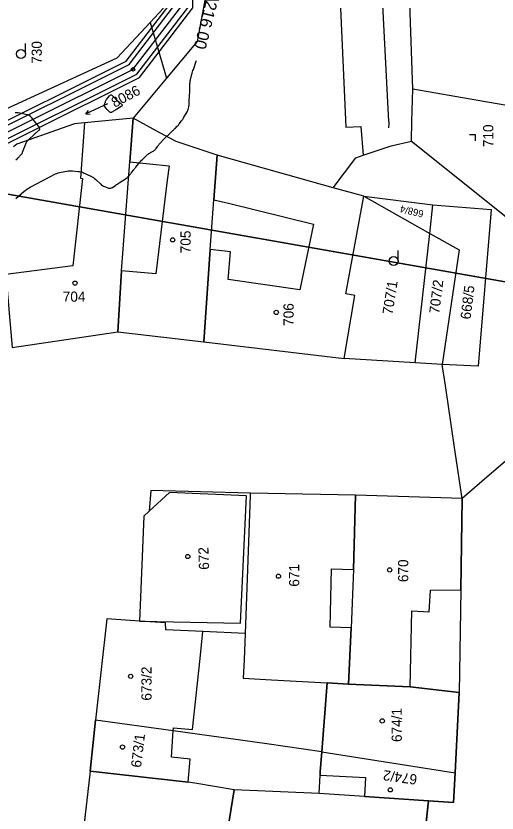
# Model space of a CAD drawing. Extents: x -534481 to -534262, y -1190577 to -1190138.
# Drawn here: x -534365.7 to -534325.5, y -1190410 to -1190343.4 of the extents above; entities that cross this region are included whole.
import ezdxf

# ---------------------------------------------------------------- set-up
doc = ezdxf.new("R2010")
doc.units = 0
for name, color, linetype in [('Bonity', 7, 'Continuous'), ('Definiční body', 7, 'Continuous'), ('Polygon budovy', 7, 'Continuous'), ('Polygon parcely', 7, 'Continuous'), ('Vrstva 17', 7, 'Continuous'), ('Vrstva 18', 7, 'Continuous'), ('Vrstva 19', 7, 'Continuous'), ('Vrstva 30', 7, 'Continuous'), ('Vrstva 32', 7, 'Continuous'), ('Vrstva 37', 7, 'Continuous'), ('Vrstva 46', 7, 'Continuous'), ('Vrstva 48', 7, 'Continuous')]:
    doc.layers.add(name, color=color, linetype=linetype)

msp = doc.modelspace()

# ---------------------------------------------------------------- linework, layer by layer
at = {"layer": 'Bonity'}
msp.add_lwpolyline([(-534409.868, -1190391.439), (-534405.947, -1190382.816), (-534400.873, -1190377.487), (-534393.696, -1190372.718), (-534384.927, -1190365.477), (-534382.631, -1190361.148), (-534355.894, -1190347.823), (-534351.738, -1190342.389), (-534351.577, -1190328.316), (-534347.204, -1190300.921), (-534345.553, -1190283.64), (-534344.682, -1190264.494)], dxfattribs=at)
at = {"layer": 'Definiční body'}
for p, q in [((-534353.09, -1190348.56), (-534355.88, -1190351.91)), ((-534336.63, -1190358.42), (-534339.19, -1190357.71)), ((-534336.63, -1190358.42), (-534330.85, -1190359.15)), ((-534336.63, -1190358.42), (-534331.12, -1190361.52)), ((-534331.12, -1190361.52), (-534330.85, -1190359.15)), ((-534332.34, -1190372.35), (-534331.12, -1190361.52)), ((-534365.97, -1190371.05), (-534357.17, -1190369.75)), ((-534357.17, -1190369.75), (-534349.98, -1190370.59)), ((-534349.98, -1190370.59), (-534338.27, -1190371.97)), ((-534332.34, -1190372.35), (-534338.27, -1190371.97)), ((-534330.07, -1190372.49), (-534332.34, -1190372.35)), ((-534337.31, -1190383.4), (-534346.1, -1190383.23)), ((-534328.4, -1190383.66), (-534337.31, -1190383.4)), ((-534358.08, -1190393.72), (-534359.01, -1190402.18)), ((-534355.36, -1190393.91), (-534358.08, -1190393.72)), ((-534340.13, -1190404.83), (-534339.69, -1190399.07)), ((-534339.69, -1190399.07), (-534337.9, -1190399.17)), ((-534328.66, -1190399.89), (-534329, -1190406.6)), ((-534359.48, -1190406.45), (-534359.01, -1190402.18)), ((-534340.26, -1190406.48), (-534340.13, -1190404.83)), ((-534340.13, -1190404.83), (-534329, -1190406.6)), ((-534359.48, -1190406.45), (-534361.32, -1190422.75)), ((-534340.34, -1190408.33), (-534347.45, -1190408.02)), ((-534331.23, -1190408.93), (-534332.91, -1190424.36))]:
    msp.add_line(p, q, dxfattribs=at)
for points in [[(-534349.69, -1190337.24), (-534349.69, -1190337.44), (-534349.9, -1190342.02), (-534350.53, -1190345.48), (-534353.09, -1190348.56)], [(-534332.53, -1190349.48), (-534332.78, -1190342.31), (-534332.83, -1190337.12)], [(-534354.46, -1190343.91), (-534353.36, -1190342.74), (-534353.4, -1190337.34)], [(-534374.45, -1190354.76), (-534357.22, -1190346.86), (-534354.46, -1190343.91)], [(-534354.46, -1190343.91), (-534354.18, -1190344.85), (-534353.82, -1190346.09), (-534353.09, -1190348.56)], [(-534332.65, -1190353.81), (-534332.6, -1190352.16), (-534332.53, -1190349.48)], [(-534315.73, -1190352.48), (-534320, -1190351.64), (-534327.1, -1190350.42), (-534332.53, -1190349.48)], [(-534355.88, -1190351.91), (-534359.93, -1190352.28), (-534360.78, -1190352.36), (-534365.58, -1190354.08), (-534365.87, -1190354.29)], [(-534357.17, -1190369.75), (-534356.84, -1190364.64), (-534356.15, -1190355.55), (-534355.88, -1190351.91)], [(-534348.86, -1190355), (-534352.29, -1190353.85), (-534353.64, -1190353.12), (-534355.88, -1190351.91)], [(-534339.19, -1190357.71), (-534337.29, -1190355.2), (-534336.67, -1190354.99), (-534334.35, -1190354.21), (-534332.65, -1190353.81)], [(-534332.65, -1190353.81), (-534323.62, -1190361.03), (-534317.88, -1190363.31), (-534317.85, -1190363.15)], [(-534349.98, -1190370.59), (-534349.44, -1190362.88), (-534349.13, -1190358.72), (-534348.86, -1190355)], [(-534339.19, -1190357.71), (-534347.58, -1190355.36), (-534348.86, -1190355)], [(-534338.27, -1190371.97), (-534337.38, -1190366.71), (-534338.11, -1190366.57), (-534336.63, -1190358.42)], [(-534330.85, -1190359.15), (-534326, -1190359.52), (-534327.08, -1190372.63), (-534330.07, -1190372.49)], [(-534331.12, -1190361.52), (-534328.67, -1190362.89), (-534330.07, -1190372.49)], [(-534328.4, -1190383.66), (-534329.04, -1190379.4), (-534329.81, -1190374.24), (-534330.07, -1190372.49)], [(-534318.86, -1190375.44), (-534321.27, -1190377.51), (-534326.78, -1190382.26), (-534328.4, -1190383.66)], [(-534346.1, -1190383.23), (-534354.41, -1190383.01), (-534354.55, -1190384.72), (-534355, -1190385.14), (-534355.36, -1190393.91)], [(-534346.1, -1190383.23), (-534346.11, -1190383.45), (-534346.53, -1190394.95)], [(-534337.31, -1190383.4), (-534337.47, -1190389.59), (-534337.69, -1190394.47), (-534337.9, -1190399.17)], [(-534328.4, -1190383.66), (-534328.51, -1190391.31), (-534328.66, -1190399.89)], [(-534346.53, -1190394.95), (-534350.05, -1190394.78), (-534353.16, -1190394.63), (-534353.18, -1190394.06), (-534355.29, -1190393.91), (-534355.36, -1190393.91)], [(-534346.53, -1190394.95), (-534346.62, -1190397.16), (-534346.69, -1190398.67), (-534344.32, -1190398.81), (-534339.69, -1190399.07)], [(-534337.9, -1190399.17), (-534332.75, -1190399.41), (-534328.66, -1190399.89)], [(-534340.13, -1190404.83), (-534344.71, -1190404.18), (-534352.53, -1190403.09), (-534359.01, -1190402.18)], [(-534347.45, -1190408.02), (-534350.73, -1190407.46), (-534351.28, -1190407.37), (-534359.48, -1190406.45)], [(-534340.34, -1190408.33), (-534340.27, -1190406.79), (-534340.26, -1190406.48)], [(-534329, -1190406.6), (-534329.13, -1190409.08), (-534331.23, -1190408.93)], [(-534347.45, -1190408.02), (-534348.24, -1190413.03), (-534349.11, -1190420.99), (-534349.31, -1190422.85)], [(-534331.23, -1190408.93), (-534336.56, -1190408.56), (-534340.34, -1190408.33)]]:
    msp.add_lwpolyline(points, dxfattribs=at)
at = {"layer": 'Polygon parcely'}
for points in [[(-534349.9, -1190342.02), (-534347.72, -1190341.99), (-534347.71, -1190342.39), (-534338.59, -1190342.1), (-534338.12, -1190352.66), (-534336.88, -1190352.6), (-534336.67, -1190354.99), (-534334.35, -1190354.21), (-534332.65, -1190353.81), (-534332.6, -1190352.16), (-534332.53, -1190349.48), (-534332.78, -1190342.31), (-534332.83, -1190337.12), (-534337.65, -1190337.15), (-534347.69, -1190337.23), (-534349.69, -1190337.24), (-534349.69, -1190337.44)], [(-534366.5, -1190364.95), (-534365.97, -1190371.05), (-534357.17, -1190369.75), (-534356.84, -1190364.64), (-534356.15, -1190355.55), (-534355.88, -1190351.91), (-534359.93, -1190352.28), (-534360.28, -1190356.91), (-534360.12, -1190356.93), (-534360.9, -1190364.23)], [(-534352.29, -1190353.85), (-534353.64, -1190353.12), (-534355.88, -1190351.91), (-534356.15, -1190355.55), (-534352.88, -1190355.89), (-534353.03, -1190357.09), (-534353.98, -1190364.91), (-534356.84, -1190364.64), (-534357.17, -1190369.75), (-534349.98, -1190370.59), (-534349.44, -1190362.88), (-534349.13, -1190358.72), (-534348.86, -1190355)], [(-534349.44, -1190362.88), (-534349.98, -1190370.59), (-534338.27, -1190371.97), (-534337.38, -1190366.71), (-534338.11, -1190366.57), (-534336.63, -1190358.42), (-534339.19, -1190357.71), (-534347.58, -1190355.36), (-534348.86, -1190355), (-534349.13, -1190358.72), (-534347.93, -1190359.01), (-534340.81, -1190360.75), (-534341.96, -1190366.24), (-534347.94, -1190365.39), (-534347.74, -1190363.06)], [(-534355.36, -1190393.91), (-534355.29, -1190393.91), (-534346.92, -1190394.09), (-534346.41, -1190383.44), (-534352.85, -1190383.16), (-534354.55, -1190384.72), (-534355, -1190385.14)], [(-534344.32, -1190398.81), (-534339.69, -1190399.07), (-534337.9, -1190399.17), (-534337.69, -1190394.47), (-534339.43, -1190394.43), (-534339.31, -1190389.56), (-534337.47, -1190389.59), (-534337.31, -1190383.4), (-534346.1, -1190383.23), (-534346.11, -1190383.45), (-534346.53, -1190394.95), (-534346.62, -1190397.16), (-534346.69, -1190398.67)], [(-534332.62, -1190393.06), (-534331.17, -1190393.14), (-534331.06, -1190391.32), (-534328.51, -1190391.31), (-534328.4, -1190383.66), (-534337.31, -1190383.4), (-534337.47, -1190389.59), (-534337.69, -1190394.47), (-534337.9, -1190399.17), (-534332.75, -1190399.41)], [(-534359.48, -1190406.45), (-534351.28, -1190407.37), (-534351.13, -1190405.45), (-534352.67, -1190405.29), (-534352.53, -1190403.09), (-534352.51, -1190402.82), (-534350.91, -1190402.96), (-534350.29, -1190397.04), (-534350.05, -1190394.78), (-534353.16, -1190394.63), (-534353.18, -1190394.06), (-534355.29, -1190393.91), (-534355.36, -1190393.91), (-534358.08, -1190393.72), (-534359.01, -1190402.18)], [(-534329, -1190406.6), (-534328.66, -1190399.89), (-534332.75, -1190399.41), (-534337.9, -1190399.17), (-534339.69, -1190399.07), (-534340.13, -1190404.83), (-534340.26, -1190406.48), (-534340.27, -1190406.79), (-534336.48, -1190406.99), (-534336.56, -1190408.56), (-534331.23, -1190408.93), (-534329.13, -1190409.08)], [(-534350.73, -1190407.46), (-534351.28, -1190407.37), (-534359.48, -1190406.45), (-534361.32, -1190422.75), (-534349.49, -1190424.31), (-534349.31, -1190422.85), (-534349.11, -1190420.99), (-534351.71, -1190420.68), (-534353.09, -1190421.73), (-534356.12, -1190421.36), (-534355.1, -1190412.3), (-534348.24, -1190413.03), (-534347.45, -1190408.02)], [(-534349.31, -1190422.85), (-534346.43, -1190423.17), (-534346.07, -1190420.03), (-534344.47, -1190420.16), (-534344.27, -1190417.73), (-534345.78, -1190417.61), (-534345.25, -1190412.99), (-534338.47, -1190413.36), (-534338.99, -1190419.24), (-534337.36, -1190419.45), (-534337.91, -1190424.11), (-534332.91, -1190424.36), (-534331.23, -1190408.93), (-534336.56, -1190408.56), (-534340.34, -1190408.33), (-534347.45, -1190408.02), (-534348.24, -1190413.03), (-534349.11, -1190420.99)]]:
    msp.add_lwpolyline(points, close=True, dxfattribs=at)
at = {"layer": 'Vrstva 18'}
for points in [[(-534334.529, -1190352.701), (-534334.503, -1190352.328), (-534334.503, -1190352.325), (-534334.501, -1190352.322), (-534334.497, -1190352.314), (-534334.496, -1190352.31), (-534334.496, -1190352.309), (-534334.498, -1190352.297), (-534334.499, -1190352.29), (-534334.517, -1190352.223), (-534334.525, -1190352.195), (-534334.526, -1190352.189), (-534334.527, -1190352.183), (-534334.528, -1190352.177), (-534334.528, -1190352.171), (-534335.719, -1190328.886)], [(-534365.666, -1190355.384), (-534365.509, -1190355.229), (-534365.471, -1190355.191), (-534365.434, -1190355.153), (-534365.397, -1190355.115), (-534365.361, -1190355.077), (-534365.216, -1190354.922), (-534365.182, -1190354.882), (-534365.152, -1190354.839), (-534365.126, -1190354.794), (-534365.105, -1190354.746), (-534364.775, -1190353.909), (-534364.763, -1190353.883), (-534364.748, -1190353.858), (-534364.731, -1190353.835), (-534364.712, -1190353.813), (-534364.63, -1190353.731), (-534364.609, -1190353.71), (-534364.588, -1190353.69), (-534364.567, -1190353.67), (-534364.546, -1190353.65), (-534363.749, -1190352.897), (-534363.743, -1190352.892), (-534363.736, -1190352.887), (-534363.722, -1190352.878), (-534363.715, -1190352.873), (-534363.708, -1190352.867), (-534363.69, -1190352.852), (-534363.686, -1190352.848), (-534363.683, -1190352.844), (-534363.681, -1190352.839), (-534363.68, -1190352.834), (-534363.678, -1190352.795), (-534363.678, -1190352.787), (-534363.679, -1190352.779), (-534363.681, -1190352.771), (-534363.683, -1190352.763), (-534363.727, -1190352.643), (-534363.736, -1190352.621), (-534363.747, -1190352.6), (-534363.759, -1190352.58), (-534363.774, -1190352.561), (-534364.346, -1190351.878), (-534364.451, -1190351.772), (-534364.568, -1190351.688), (-534364.699, -1190351.626), (-534364.842, -1190351.586), (-534365.49, -1190351.461), (-534365.614, -1190351.448), (-534365.733, -1190351.46)]]:
    msp.add_lwpolyline(points, dxfattribs=at)
msp.add_lwpolyline([(-534357.697, -1190351.419), (-534357.741, -1190351.423), (-534357.783, -1190351.412), (-534357.825, -1190351.384), (-534357.995, -1190351.236), (-534358.031, -1190351.202), (-534358.065, -1190351.167), (-534358.097, -1190351.129), (-534358.126, -1190351.089), (-534358.239, -1190350.926), (-534358.262, -1190350.885), (-534358.273, -1190350.841), (-534358.274, -1190350.797), (-534358.265, -1190350.75), (-534358.194, -1190350.532), (-534358.175, -1190350.481), (-534358.152, -1190350.432), (-534358.124, -1190350.385), (-534358.093, -1190350.341), (-534357.846, -1190350.019), (-534357.794, -1190349.968), (-534357.739, -1190349.948), (-534357.682, -1190349.961), (-534357.623, -1190350.005), (-534357.383, -1190350.245), (-534357.323, -1190350.304), (-534357.262, -1190350.363), (-534357.199, -1190350.421), (-534357.136, -1190350.477), (-534356.855, -1190350.725), (-534356.805, -1190350.783), (-534356.792, -1190350.837), (-534356.816, -1190350.888), (-534356.876, -1190350.935), (-534357.272, -1190351.165), (-534357.319, -1190351.193), (-534357.367, -1190351.221), (-534357.414, -1190351.25), (-534357.461, -1190351.279), (-534357.651, -1190351.398)], close=True, dxfattribs=at)
at = {"layer": 'Vrstva 19'}
msp.add_lwpolyline([(-534365.672, -1190358.609), (-534365.014, -1190358.03), (-534364.89, -1190357.928), (-534364.76, -1190357.833), (-534364.625, -1190357.746), (-534364.484, -1190357.667), (-534362.353, -1190356.56), (-534362.244, -1190356.509), (-534362.133, -1190356.467), (-534362.018, -1190356.433), (-534361.9, -1190356.408), (-534361.422, -1190356.327), (-534361.304, -1190356.311), (-534361.185, -1190356.302), (-534361.066, -1190356.3), (-534360.946, -1190356.305), (-534360.467, -1190356.342), (-534360.349, -1190356.356), (-534360.233, -1190356.381), (-534360.12, -1190356.416), (-534360.01, -1190356.462), (-534359.42, -1190356.737), (-534359.307, -1190356.795), (-534359.2, -1190356.862), (-534359.099, -1190356.938), (-534359.005, -1190357.022), (-534358.588, -1190357.425), (-534358.518, -1190357.486), (-534358.443, -1190357.537), (-534358.362, -1190357.58), (-534358.276, -1190357.613), (-534357.904, -1190357.735), (-534357.825, -1190357.752), (-534357.749, -1190357.75), (-534357.675, -1190357.73), (-534357.604, -1190357.69), (-534357.326, -1190357.497), (-534357.257, -1190357.449), (-534357.187, -1190357.401), (-534357.116, -1190357.354), (-534357.046, -1190357.307), (-534356.43, -1190356.903), (-534356.387, -1190356.872), (-534356.346, -1190356.839), (-534356.309, -1190356.802), (-534356.274, -1190356.763), (-534356.139, -1190356.599), (-534356.105, -1190356.557), (-534356.071, -1190356.516), (-534356.038, -1190356.475), (-534356.005, -1190356.433), (-534355.825, -1190356.207), (-534355.784, -1190356.155), (-534355.743, -1190356.104), (-534355.701, -1190356.052), (-534355.66, -1190356.001), (-534355.309, -1190355.573), (-534355.242, -1190355.493), (-534355.172, -1190355.416), (-534355.099, -1190355.341), (-534355.023, -1190355.269), (-534354.673, -1190354.947), (-534354.616, -1190354.897), (-534354.556, -1190354.852), (-534354.494, -1190354.81), (-534354.429, -1190354.772), (-534354.148, -1190354.619), (-534354.092, -1190354.584), (-534354.043, -1190354.544), (-534353.999, -1190354.498), (-534353.96, -1190354.446), (-534353.815, -1190354.225), (-534353.778, -1190354.171), (-534353.738, -1190354.119), (-534353.697, -1190354.068), (-534353.652, -1190354.02), (-534353.278, -1190353.627), (-534353.2, -1190353.546), (-534353.122, -1190353.466), (-534353.042, -1190353.387), (-534352.961, -1190353.309), (-534352.566, -1190352.933), (-534352.519, -1190352.889), (-534352.473, -1190352.844), (-534352.426, -1190352.8), (-534352.38, -1190352.755), (-534352.195, -1190352.575), (-534352.149, -1190352.53), (-534352.106, -1190352.482), (-534352.064, -1190352.433), (-534352.025, -1190352.382), (-534351.833, -1190352.126), (-534351.789, -1190352.066), (-534351.747, -1190352.004), (-534351.706, -1190351.941), (-534351.668, -1190351.877), (-534351.37, -1190351.369), (-534351.344, -1190351.321), (-534351.321, -1190351.271), (-534351.302, -1190351.219), (-534351.286, -1190351.166), (-534351.231, -1190350.952), (-534351.219, -1190350.898), (-534351.21, -1190350.844), (-534351.204, -1190350.789), (-534351.201, -1190350.734), (-534351.193, -1190350.429), (-534351.191, -1190350.36), (-534351.189, -1190350.291), (-534351.186, -1190350.222), (-534351.183, -1190350.153), (-534351.155, -1190349.589), (-534351.151, -1190349.515), (-534351.148, -1190349.44), (-534351.146, -1190349.366), (-534351.144, -1190349.291), (-534351.136, -1190348.993), (-534351.132, -1190348.919), (-534351.124, -1190348.846), (-534351.112, -1190348.773), (-534351.096, -1190348.7), (-534350.976, -1190348.23), (-534350.949, -1190348.128), (-534350.919, -1190348.027), (-534350.887, -1190347.926), (-534350.853, -1190347.827), (-534350.604, -1190347.137), (-534350.585, -1190347.09)], dxfattribs=at)
at = {"layer": 'Vrstva 30'}
for points in [[(-534279.901, -1190266.866), (-534426.145, -1190241.079), (-534444.378, -1190344.484), (-534298.134, -1190370.27)], [(-534298.134, -1190370.27), (-534444.378, -1190344.484), (-534462.611, -1190447.888), (-534316.367, -1190473.675)]]:
    msp.add_lwpolyline(points, dxfattribs=at)
at = {"layer": 'Vrstva 32'}
for points in [[(-534409.97, -1190389.61), (-534406.662, -1190382.333), (-534401.423, -1190376.832), (-534394.204, -1190372.034), (-534385.599, -1190364.929), (-534383.254, -1190360.509), (-534356.45, -1190347.15), (-534352.584, -1190342.096), (-534352.426, -1190328.244), (-534348.048, -1190300.813), (-534346.401, -1190283.581), (-534345.607, -1190266.12)], [(-534409.916, -1190390.337), (-534406.368, -1190382.532), (-534401.196, -1190377.102), (-534393.995, -1190372.316), (-534385.322, -1190365.155), (-534382.997, -1190360.772), (-534356.221, -1190347.427), (-534352.236, -1190342.217), (-534352.076, -1190328.274), (-534347.7, -1190300.857), (-534346.052, -1190283.605), (-534345.255, -1190266.096)], [(-534409.363, -1190391.537), (-534405.527, -1190383.099), (-534400.549, -1190377.873), (-534393.398, -1190373.12), (-534384.532, -1190365.799), (-534382.264, -1190361.524), (-534355.568, -1190348.219), (-534351.24, -1190342.56), (-534351.077, -1190328.359), (-534346.708, -1190300.984), (-534345.054, -1190283.675), (-534344.256, -1190266.142)], [(-534409.02, -1190391.627), (-534405.233, -1190383.298), (-534400.323, -1190378.142), (-534393.189, -1190373.401), (-534384.256, -1190366.025), (-534382.008, -1190361.787), (-534355.339, -1190348.496), (-534350.891, -1190342.681), (-534350.728, -1190328.388), (-534346.36, -1190301.028), (-534344.705, -1190283.7), (-534343.908, -1190266.201)]]:
    msp.add_lwpolyline(points, dxfattribs=at)
at = {"layer": 'Vrstva 37'}
msp.add_circle((-534355.894, -1190347.823), 0.15, dxfattribs=at)
msp.add_circle((-534355.894, -1190347.823), 0.15, dxfattribs=at)
msp.add_circle((-534355.894, -1190347.823), 0.15, dxfattribs=at)
msp.add_circle((-534355.894, -1190347.823), 0.15, dxfattribs=at)
msp.add_circle((-534355.894, -1190347.823), 0.15, dxfattribs=at)
msp.add_circle((-534355.894, -1190347.823), 0.15, dxfattribs=at)
at = {"layer": 'Vrstva 46'}
for centre in [(-534352.583, -1190362.067), (-534360.736, -1190365.678), (-534343.931, -1190368.127), (-534351.316, -1190388.519), (-534334.462, -1190389.638), (-534343.75, -1190390.164), (-534356.08, -1190398.534), (-534335.084, -1190402.254), (-534356.766, -1190404.44), (-534334.413, -1190408.014)]:
    msp.add_circle(centre, 0.175, dxfattribs=at)
at = {"layer": 'Vrstva 48'}
for p, q in [((-534364.874, -1190346.532), (-534364.874, -1190345.657)), ((-534358.009, -1190350.696), (-534359.829, -1190351.549)), ((-534359.829, -1190351.549), (-534359.604, -1190351.258)), ((-534359.829, -1190351.549), (-534359.461, -1190351.562)), ((-534327.29, -1190353.278), (-534327.79, -1190353.278)), ((-534327.29, -1190353.779), (-534327.29, -1190353.278)), ((-534333.751, -1190363.838), (-534333.751, -1190362.963))]:
    msp.add_line(p, q, dxfattribs=at)
for centre in [(-534365.249, -1190346.532), (-534334.126, -1190363.838)]:
    msp.add_circle(centre, 0.375, dxfattribs=at)

# ---------------------------------------------------------------- texts
at = {"layer": 'Polygon budovy'}
for s, height, rotation, p in [('730', 0.85, 90, (-534363.504, -1190347.355)), ('8086', 0.85, 27.99023, (-534357.42, -1190351.038)), ('710', 0.85, 90, (-534325.811, -1190354.319)), ('668/4', 0.595, 166.30823, (-534331.579, -1190359.639)), ('705', 0.85, 90, (-534351.077, -1190363.185)), ('707/1', 0.85, 81, (-534334.236, -1190368.354)), ('707/2', 0.85, 83, (-534330.323, -1190368.274)), ('668/5', 0.85, 83, (-534327.72, -1190368.744)), ('706', 0.85, 90, (-534342.477, -1190369.251)), ('672', 0.85, 92, (-534349.53, -1190389.612)), ('671', 0.85, 90, (-534342.014, -1190391.039)), ('670', 0.85, 90, (-534332.912, -1190390.658)), ('673/2', 0.85, 90, (-534354.34, -1190400.558)), ('674/1', 0.85, 90, (-534333.45, -1190404.016)), ('673/1', 0.85, 83, (-534355.227, -1190406.191)), ('674/2', 0.85, 172, (-534332.124, -1190406.752))]:
    msp.add_text(s, height=height, rotation=rotation, dxfattribs=at).set_placement(p)
msp.add_text('704', height=0.85, dxfattribs=at).set_placement((-534361.756, -1190367.231))
at = {"layer": 'Vrstva 17'}
msp.add_text('216.00', height=1, rotation=255.7671, dxfattribs=at).set_placement((-534349.81, -1190342.023))

doc.saveas('drawing.dxf')
